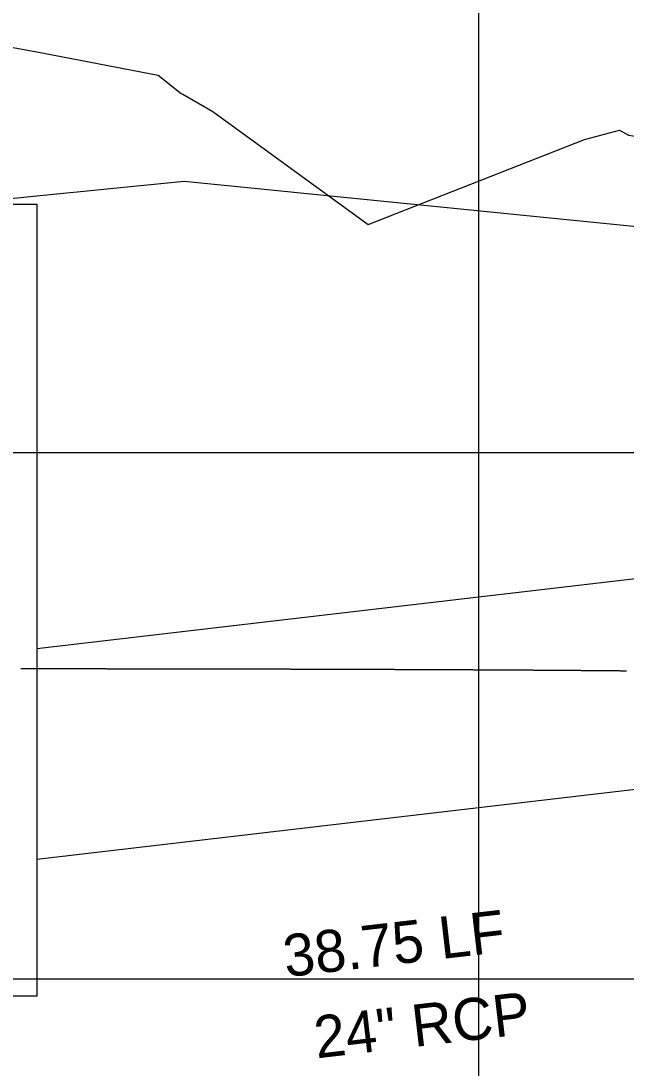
# Model space of a CAD drawing. Extents: x 2252703 to 2264864, y 13787568 to 13790989.
# Drawn here: x 2264616.92 to 2264645.67, y 13788381.55 to 13788431.28 of the extents above; entities that cross this region are included whole.
import ezdxf

# ---------------------------------------------------------------- set-up
doc = ezdxf.new("R2010")
doc.units = 0
for name, color, linetype in [('BORD_grid_bottom_major_5int', 7, 'Continuous'), ('D_DRN_PROF_HGL', 7, 'Continuous'), ('D_PROF_1', 7, 'Continuous'), ('D_PROF_NOTES_1', 7, 'Continuous'), ('Drain_PipeInside', 7, 'Continuous'), ('E_Terrain', 7, 'Continuous'), ('Inlet', 7, 'Continuous'), ('z - Construction', 7, 'Continuous')]:
    doc.layers.add(name, color=color, linetype=linetype)

msp = doc.modelspace()

# ---------------------------------------------------------------- linework, layer by layer
at = {"layer": 'BORD_grid_bottom_major_5int'}
for p, q in [((2264638.672, 13788310.788), (2264638.672, 13788610.788)), ((2264413.672, 13788410.788), (2264763.672, 13788410.788)), ((2264413.672, 13788385.788), (2264763.672, 13788385.788))]:
    msp.add_line(p, q, dxfattribs=at)
at = {"layer": 'D_DRN_PROF_HGL'}
msp.add_lwpolyline([(2264616.909, 13788400.52), (2264616.952, 13788400.52), (2264616.994, 13788400.52), (2264617.037, 13788400.52), (2264617.079, 13788400.52), (2264617.122, 13788400.52), (2264617.164, 13788400.52), (2264617.207, 13788400.52), (2264617.249, 13788400.519), (2264617.292, 13788400.519), (2264617.334, 13788400.519), (2264617.377, 13788400.519), (2264617.419, 13788400.519), (2264617.462, 13788400.519), (2264617.505, 13788400.519), (2264617.547, 13788400.519), (2264617.59, 13788400.519), (2264617.632, 13788400.519), (2264617.675, 13788400.519), (2264617.717, 13788400.519), (2264617.76, 13788400.519), (2264617.802, 13788400.519), (2264617.845, 13788400.519), (2264617.887, 13788400.519), (2264617.93, 13788400.519), (2264617.972, 13788400.519), (2264618.015, 13788400.519), (2264618.057, 13788400.519), (2264618.1, 13788400.519), (2264618.142, 13788400.519), (2264618.185, 13788400.519), (2264618.227, 13788400.519), (2264618.27, 13788400.519), (2264618.312, 13788400.518), (2264618.355, 13788400.518), (2264618.397, 13788400.518), (2264618.44, 13788400.518), (2264618.482, 13788400.518), (2264618.525, 13788400.518), (2264618.567, 13788400.518), (2264618.61, 13788400.518), (2264618.652, 13788400.518), (2264618.695, 13788400.518), (2264618.737, 13788400.518), (2264618.78, 13788400.518), (2264618.822, 13788400.518), (2264618.865, 13788400.518), (2264618.907, 13788400.518), (2264618.95, 13788400.518), (2264618.992, 13788400.518), (2264619.035, 13788400.518), (2264619.077, 13788400.518), (2264619.12, 13788400.518), (2264619.162, 13788400.518), (2264619.204, 13788400.518), (2264619.247, 13788400.518), (2264619.289, 13788400.517), (2264619.332, 13788400.517), (2264619.374, 13788400.517), (2264619.417, 13788400.517), (2264619.459, 13788400.517), (2264619.502, 13788400.517), (2264619.544, 13788400.517), (2264619.587, 13788400.517), (2264619.629, 13788400.517), (2264619.672, 13788400.517), (2264619.714, 13788400.517), (2264619.756, 13788400.517), (2264619.799, 13788400.517), (2264619.841, 13788400.517), (2264619.884, 13788400.517), (2264619.926, 13788400.517), (2264619.969, 13788400.517), (2264620.011, 13788400.517), (2264620.054, 13788400.517), (2264620.096, 13788400.517), (2264620.138, 13788400.516), (2264620.181, 13788400.516), (2264620.223, 13788400.516), (2264620.266, 13788400.516), (2264620.308, 13788400.516), (2264620.351, 13788400.516), (2264620.393, 13788400.516), (2264620.435, 13788400.516), (2264620.478, 13788400.516), (2264620.52, 13788400.516), (2264620.563, 13788400.516), (2264620.605, 13788400.516), (2264620.648, 13788400.516), (2264620.69, 13788400.516), (2264620.732, 13788400.516), (2264620.775, 13788400.516), (2264620.817, 13788400.516), (2264620.86, 13788400.516), (2264620.902, 13788400.516), (2264620.944, 13788400.516), (2264620.987, 13788400.515), (2264621.029, 13788400.515), (2264621.072, 13788400.515), (2264621.114, 13788400.515), (2264621.156, 13788400.515), (2264621.199, 13788400.515), (2264621.241, 13788400.515), (2264621.284, 13788400.515), (2264621.326, 13788400.515), (2264621.368, 13788400.515), (2264621.411, 13788400.515), (2264621.453, 13788400.515), (2264621.496, 13788400.515), (2264621.538, 13788400.515), (2264621.58, 13788400.515), (2264621.623, 13788400.515), (2264621.665, 13788400.515), (2264621.707, 13788400.515), (2264621.75, 13788400.514), (2264621.792, 13788400.514), (2264621.835, 13788400.514), (2264621.877, 13788400.514), (2264621.919, 13788400.514), (2264621.962, 13788400.514), (2264622.004, 13788400.514), (2264622.046, 13788400.514), (2264622.089, 13788400.514), (2264622.131, 13788400.514), (2264622.173, 13788400.514), (2264622.216, 13788400.514), (2264622.258, 13788400.514), (2264622.3, 13788400.514), (2264622.343, 13788400.514), (2264622.385, 13788400.514), (2264622.428, 13788400.514), (2264622.47, 13788400.513), (2264622.512, 13788400.513), (2264622.555, 13788400.513), (2264622.597, 13788400.513), (2264622.639, 13788400.513), (2264622.682, 13788400.513), (2264622.724, 13788400.513), (2264622.766, 13788400.513), (2264622.809, 13788400.513), (2264622.851, 13788400.513), (2264622.893, 13788400.513), (2264622.936, 13788400.513), (2264622.978, 13788400.513), (2264623.02, 13788400.513), (2264623.063, 13788400.513), (2264623.105, 13788400.513), (2264623.147, 13788400.512), (2264623.189, 13788400.512), (2264623.232, 13788400.512), (2264623.274, 13788400.512), (2264623.316, 13788400.512), (2264623.359, 13788400.512), (2264623.401, 13788400.512), (2264623.443, 13788400.512), (2264623.486, 13788400.512), (2264623.528, 13788400.512), (2264623.57, 13788400.512), (2264623.613, 13788400.512), (2264623.655, 13788400.512), (2264623.697, 13788400.512), (2264623.739, 13788400.512), (2264623.782, 13788400.511), (2264623.824, 13788400.511), (2264623.866, 13788400.511), (2264623.909, 13788400.511), (2264623.951, 13788400.511), (2264623.993, 13788400.511), (2264624.035, 13788400.511), (2264624.078, 13788400.511), (2264624.12, 13788400.511), (2264624.162, 13788400.511), (2264624.205, 13788400.511), (2264624.247, 13788400.511), (2264624.289, 13788400.511), (2264624.331, 13788400.511), (2264624.374, 13788400.511), (2264624.416, 13788400.51), (2264624.458, 13788400.51), (2264624.5, 13788400.51), (2264624.543, 13788400.51), (2264624.585, 13788400.51), (2264624.627, 13788400.51), (2264624.669, 13788400.51), (2264624.712, 13788400.51), (2264624.754, 13788400.51), (2264624.796, 13788400.51), (2264624.838, 13788400.51), (2264624.881, 13788400.51), (2264624.923, 13788400.51), (2264624.965, 13788400.509), (2264625.007, 13788400.509), (2264625.049, 13788400.509), (2264625.092, 13788400.509), (2264625.134, 13788400.509), (2264625.176, 13788400.509), (2264625.218, 13788400.509), (2264625.261, 13788400.509), (2264625.303, 13788400.509), (2264625.345, 13788400.509), (2264625.387, 13788400.509), (2264625.429, 13788400.509), (2264625.472, 13788400.509), (2264625.514, 13788400.509), (2264625.556, 13788400.508), (2264625.598, 13788400.508), (2264625.641, 13788400.508), (2264625.683, 13788400.508), (2264625.725, 13788400.508), (2264625.767, 13788400.508), (2264625.809, 13788400.508), (2264625.851, 13788400.508), (2264625.894, 13788400.508), (2264625.936, 13788400.508), (2264625.978, 13788400.508), (2264626.02, 13788400.508), (2264626.062, 13788400.507), (2264626.105, 13788400.507), (2264626.147, 13788400.507), (2264626.189, 13788400.507), (2264626.231, 13788400.507), (2264626.273, 13788400.507), (2264626.315, 13788400.507), (2264626.358, 13788400.507), (2264626.4, 13788400.507), (2264626.442, 13788400.507), (2264626.484, 13788400.507), (2264626.526, 13788400.507), (2264626.568, 13788400.507), (2264626.611, 13788400.506), (2264626.653, 13788400.506), (2264626.695, 13788400.506), (2264626.737, 13788400.506), (2264626.779, 13788400.506), (2264626.821, 13788400.506), (2264626.863, 13788400.506), (2264626.906, 13788400.506), (2264626.948, 13788400.506), (2264626.99, 13788400.506), (2264627.032, 13788400.506), (2264627.074, 13788400.506), (2264627.116, 13788400.505), (2264627.158, 13788400.505), (2264627.2, 13788400.505), (2264627.243, 13788400.505), (2264627.285, 13788400.505), (2264627.327, 13788400.505), (2264627.369, 13788400.505), (2264627.411, 13788400.505), (2264627.453, 13788400.505), (2264627.495, 13788400.505), (2264627.537, 13788400.505), (2264627.579, 13788400.504), (2264627.622, 13788400.504), (2264627.664, 13788400.504), (2264627.706, 13788400.504), (2264627.748, 13788400.504), (2264627.79, 13788400.504), (2264627.832, 13788400.504), (2264627.874, 13788400.504), (2264627.916, 13788400.504), (2264627.958, 13788400.504), (2264628, 13788400.504), (2264628.042, 13788400.503), (2264628.084, 13788400.503), (2264628.126, 13788400.503), (2264628.169, 13788400.503), (2264628.211, 13788400.503), (2264628.253, 13788400.503), (2264628.295, 13788400.503), (2264628.337, 13788400.503), (2264628.379, 13788400.503), (2264628.421, 13788400.503), (2264628.463, 13788400.503), (2264628.505, 13788400.502), (2264628.547, 13788400.502), (2264628.589, 13788400.502), (2264628.631, 13788400.502), (2264628.673, 13788400.502), (2264628.715, 13788400.502), (2264628.757, 13788400.502), (2264628.799, 13788400.502), (2264628.841, 13788400.502), (2264628.883, 13788400.502), (2264628.925, 13788400.501), (2264628.967, 13788400.501), (2264629.009, 13788400.501), (2264629.051, 13788400.501), (2264629.093, 13788400.501), (2264629.135, 13788400.501), (2264629.177, 13788400.501), (2264629.219, 13788400.501), (2264629.261, 13788400.501), (2264629.303, 13788400.501), (2264629.345, 13788400.5), (2264629.387, 13788400.5), (2264629.429, 13788400.5), (2264629.471, 13788400.5), (2264629.513, 13788400.5), (2264629.555, 13788400.5), (2264629.597, 13788400.5), (2264629.639, 13788400.5), (2264629.681, 13788400.5), (2264629.723, 13788400.5), (2264629.765, 13788400.499), (2264629.807, 13788400.499), (2264629.849, 13788400.499), (2264629.891, 13788400.499), (2264629.933, 13788400.499), (2264629.975, 13788400.499), (2264630.017, 13788400.499), (2264630.059, 13788400.499), (2264630.101, 13788400.499), (2264630.143, 13788400.498), (2264630.185, 13788400.498), (2264630.227, 13788400.498), (2264630.268, 13788400.498), (2264630.31, 13788400.498), (2264630.352, 13788400.498), (2264630.394, 13788400.498), (2264630.436, 13788400.498), (2264630.478, 13788400.498), (2264630.52, 13788400.497), (2264630.562, 13788400.497), (2264630.604, 13788400.497), (2264630.646, 13788400.497), (2264630.688, 13788400.497), (2264630.729, 13788400.497), (2264630.771, 13788400.497), (2264630.813, 13788400.497), (2264630.855, 13788400.497), (2264630.897, 13788400.496), (2264630.939, 13788400.496), (2264630.981, 13788400.496), (2264631.023, 13788400.496), (2264631.065, 13788400.496), (2264631.106, 13788400.496), (2264631.148, 13788400.496), (2264631.19, 13788400.496), (2264631.232, 13788400.496), (2264631.274, 13788400.495), (2264631.316, 13788400.495), (2264631.358, 13788400.495), (2264631.399, 13788400.495), (2264631.441, 13788400.495), (2264631.483, 13788400.495), (2264631.525, 13788400.495), (2264631.567, 13788400.495), (2264631.609, 13788400.494), (2264631.65, 13788400.494), (2264631.692, 13788400.494), (2264631.734, 13788400.494), (2264631.776, 13788400.494), (2264631.818, 13788400.494), (2264631.86, 13788400.494), (2264631.901, 13788400.494), (2264631.943, 13788400.493), (2264631.985, 13788400.493), (2264632.027, 13788400.493), (2264632.069, 13788400.493), (2264632.11, 13788400.493), (2264632.152, 13788400.493), (2264632.194, 13788400.493), (2264632.236, 13788400.493), (2264632.277, 13788400.492), (2264632.319, 13788400.492), (2264632.361, 13788400.492), (2264632.403, 13788400.492), (2264632.445, 13788400.492), (2264632.486, 13788400.492), (2264632.528, 13788400.492), (2264632.57, 13788400.492), (2264632.612, 13788400.491), (2264632.653, 13788400.491), (2264632.695, 13788400.491), (2264632.737, 13788400.491), (2264632.779, 13788400.491), (2264632.82, 13788400.491), (2264632.862, 13788400.491), (2264632.904, 13788400.491), (2264632.945, 13788400.49), (2264632.987, 13788400.49), (2264633.029, 13788400.49), (2264633.071, 13788400.49), (2264633.112, 13788400.49), (2264633.154, 13788400.49), (2264633.196, 13788400.49), (2264633.237, 13788400.489), (2264633.279, 13788400.489), (2264633.321, 13788400.489), (2264633.362, 13788400.489), (2264633.404, 13788400.489), (2264633.446, 13788400.489), (2264633.488, 13788400.489), (2264633.529, 13788400.488), (2264633.571, 13788400.488), (2264633.613, 13788400.488), (2264633.654, 13788400.488), (2264633.696, 13788400.488), (2264633.737, 13788400.488), (2264633.779, 13788400.488), (2264633.821, 13788400.487), (2264633.862, 13788400.487), (2264633.904, 13788400.487), (2264633.946, 13788400.487), (2264633.987, 13788400.487), (2264634.029, 13788400.487), (2264634.071, 13788400.487), (2264634.112, 13788400.486), (2264634.154, 13788400.486), (2264634.195, 13788400.486), (2264634.237, 13788400.486), (2264634.279, 13788400.486), (2264634.32, 13788400.486), (2264634.362, 13788400.486), (2264634.403, 13788400.485), (2264634.445, 13788400.485), (2264634.487, 13788400.485), (2264634.528, 13788400.485), (2264634.57, 13788400.485), (2264634.611, 13788400.485), (2264634.653, 13788400.485), (2264634.694, 13788400.484), (2264634.736, 13788400.484), (2264634.777, 13788400.484), (2264634.819, 13788400.484), (2264634.861, 13788400.484), (2264634.902, 13788400.484), (2264634.944, 13788400.483), (2264634.985, 13788400.483), (2264635.027, 13788400.483), (2264635.068, 13788400.483), (2264635.11, 13788400.483), (2264635.151, 13788400.483), (2264635.193, 13788400.483), (2264635.234, 13788400.482), (2264635.276, 13788400.482), (2264635.317, 13788400.482), (2264635.359, 13788400.482), (2264635.4, 13788400.482), (2264635.442, 13788400.482), (2264635.483, 13788400.481), (2264635.525, 13788400.481), (2264635.566, 13788400.481), (2264635.608, 13788400.481), (2264635.649, 13788400.481), (2264635.691, 13788400.481), (2264635.732, 13788400.48), (2264635.773, 13788400.48), (2264635.815, 13788400.48), (2264635.856, 13788400.48), (2264635.898, 13788400.48), (2264635.939, 13788400.48), (2264635.981, 13788400.479), (2264636.022, 13788400.479), (2264636.063, 13788400.479), (2264636.105, 13788400.479), (2264636.146, 13788400.479), (2264636.188, 13788400.479), (2264636.229, 13788400.478), (2264636.27, 13788400.478), (2264636.312, 13788400.478), (2264636.353, 13788400.478), (2264636.395, 13788400.478), (2264636.436, 13788400.478), (2264636.477, 13788400.477), (2264636.519, 13788400.477), (2264636.56, 13788400.477), (2264636.601, 13788400.477), (2264636.643, 13788400.477), (2264636.684, 13788400.476), (2264636.725, 13788400.476), (2264636.767, 13788400.476), (2264636.808, 13788400.476), (2264636.849, 13788400.476), (2264636.891, 13788400.476), (2264636.932, 13788400.475), (2264636.973, 13788400.475), (2264637.015, 13788400.475), (2264637.056, 13788400.475), (2264637.097, 13788400.475), (2264637.138, 13788400.474), (2264637.18, 13788400.474), (2264637.221, 13788400.474), (2264637.262, 13788400.474), (2264637.304, 13788400.474), (2264637.345, 13788400.474), (2264637.386, 13788400.473), (2264637.427, 13788400.473), (2264637.469, 13788400.473), (2264637.51, 13788400.473), (2264637.551, 13788400.473), (2264637.592, 13788400.472), (2264637.634, 13788400.472), (2264637.675, 13788400.472), (2264637.716, 13788400.472), (2264637.757, 13788400.472), (2264637.798, 13788400.471), (2264637.84, 13788400.471), (2264637.881, 13788400.471), (2264637.922, 13788400.471), (2264637.963, 13788400.471), (2264638.004, 13788400.47), (2264638.045, 13788400.47), (2264638.087, 13788400.47), (2264638.128, 13788400.47), (2264638.169, 13788400.47), (2264638.21, 13788400.469), (2264638.251, 13788400.469), (2264638.292, 13788400.469), (2264638.333, 13788400.469), (2264638.375, 13788400.469), (2264638.416, 13788400.468), (2264638.457, 13788400.468), (2264638.498, 13788400.468), (2264638.539, 13788400.468), (2264638.58, 13788400.468), (2264638.621, 13788400.467), (2264638.662, 13788400.467), (2264638.703, 13788400.467), (2264638.744, 13788400.467), (2264638.785, 13788400.467), (2264638.827, 13788400.466), (2264638.868, 13788400.466), (2264638.909, 13788400.466), (2264638.95, 13788400.466), (2264638.991, 13788400.466), (2264639.032, 13788400.465), (2264639.073, 13788400.465), (2264639.114, 13788400.465), (2264639.155, 13788400.465), (2264639.196, 13788400.464), (2264639.237, 13788400.464), (2264639.278, 13788400.464), (2264639.319, 13788400.464), (2264639.36, 13788400.464), (2264639.401, 13788400.463), (2264639.442, 13788400.463), (2264639.483, 13788400.463), (2264639.524, 13788400.463), (2264639.564, 13788400.462), (2264639.605, 13788400.462), (2264639.646, 13788400.462), (2264639.687, 13788400.462), (2264639.728, 13788400.462), (2264639.769, 13788400.461), (2264639.81, 13788400.461), (2264639.851, 13788400.461), (2264639.892, 13788400.461), (2264639.933, 13788400.46), (2264639.974, 13788400.46), (2264640.014, 13788400.46), (2264640.055, 13788400.46), (2264640.096, 13788400.459), (2264640.137, 13788400.459), (2264640.178, 13788400.459), (2264640.219, 13788400.459), (2264640.259, 13788400.459), (2264640.3, 13788400.458), (2264640.341, 13788400.458), (2264640.382, 13788400.458), (2264640.423, 13788400.458), (2264640.463, 13788400.457), (2264640.504, 13788400.457), (2264640.545, 13788400.457), (2264640.586, 13788400.457), (2264640.627, 13788400.456), (2264640.667, 13788400.456), (2264640.708, 13788400.456), (2264640.749, 13788400.456), (2264640.79, 13788400.455), (2264640.83, 13788400.455), (2264640.871, 13788400.455), (2264640.912, 13788400.455), (2264640.952, 13788400.454), (2264640.993, 13788400.454), (2264641.034, 13788400.454), (2264641.075, 13788400.454), (2264641.115, 13788400.453), (2264641.156, 13788400.453), (2264641.197, 13788400.453), (2264641.237, 13788400.453), (2264641.278, 13788400.452), (2264641.318, 13788400.452), (2264641.359, 13788400.452), (2264641.4, 13788400.452), (2264641.44, 13788400.451), (2264641.481, 13788400.451), (2264641.522, 13788400.451), (2264641.562, 13788400.45), (2264641.603, 13788400.45), (2264641.643, 13788400.45), (2264641.684, 13788400.45), (2264641.724, 13788400.449), (2264641.765, 13788400.449), (2264641.805, 13788400.449), (2264641.846, 13788400.449), (2264641.887, 13788400.448), (2264641.927, 13788400.448), (2264641.968, 13788400.448), (2264642.008, 13788400.447), (2264642.049, 13788400.447), (2264642.089, 13788400.447), (2264642.129, 13788400.447), (2264642.17, 13788400.446), (2264642.21, 13788400.446), (2264642.251, 13788400.446), (2264642.291, 13788400.446), (2264642.332, 13788400.445), (2264642.372, 13788400.445), (2264642.413, 13788400.445), (2264642.453, 13788400.444), (2264642.493, 13788400.444), (2264642.534, 13788400.444), (2264642.574, 13788400.444), (2264642.614, 13788400.443), (2264642.655, 13788400.443), (2264642.695, 13788400.443), (2264642.736, 13788400.442), (2264642.776, 13788400.442), (2264642.816, 13788400.442), (2264642.857, 13788400.441), (2264642.897, 13788400.441), (2264642.937, 13788400.441), (2264642.977, 13788400.441), (2264643.018, 13788400.44), (2264643.058, 13788400.44), (2264643.098, 13788400.44), (2264643.138, 13788400.439), (2264643.179, 13788400.439), (2264643.219, 13788400.439), (2264643.259, 13788400.438), (2264643.299, 13788400.438), (2264643.34, 13788400.438), (2264643.38, 13788400.437), (2264643.42, 13788400.437), (2264643.46, 13788400.437), (2264643.5, 13788400.437), (2264643.54, 13788400.436), (2264643.581, 13788400.436), (2264643.621, 13788400.436), (2264643.661, 13788400.435), (2264643.701, 13788400.435), (2264643.741, 13788400.435), (2264643.781, 13788400.434), (2264643.821, 13788400.434), (2264643.861, 13788400.434), (2264643.901, 13788400.433), (2264643.941, 13788400.433), (2264643.981, 13788400.433), (2264644.021, 13788400.432), (2264644.061, 13788400.432), (2264644.101, 13788400.432), (2264644.141, 13788400.431), (2264644.181, 13788400.431), (2264644.221, 13788400.431), (2264644.261, 13788400.43), (2264644.301, 13788400.43), (2264644.341, 13788400.43), (2264644.381, 13788400.429), (2264644.421, 13788400.429), (2264644.461, 13788400.429), (2264644.501, 13788400.428), (2264644.541, 13788400.428), (2264644.581, 13788400.428), (2264644.621, 13788400.427), (2264644.66, 13788400.427), (2264644.7, 13788400.427), (2264644.74, 13788400.426), (2264644.78, 13788400.426), (2264644.82, 13788400.425), (2264644.86, 13788400.425), (2264644.899, 13788400.425), (2264644.939, 13788400.424), (2264644.979, 13788400.424), (2264645.019, 13788400.424), (2264645.058, 13788400.423), (2264645.098, 13788400.423), (2264645.138, 13788400.423), (2264645.178, 13788400.422), (2264645.217, 13788400.422), (2264645.257, 13788400.421), (2264645.297, 13788400.421), (2264645.336, 13788400.421), (2264645.376, 13788400.42), (2264645.416, 13788400.42), (2264645.455, 13788400.42), (2264645.495, 13788400.419), (2264645.534, 13788400.419), (2264645.574, 13788400.418), (2264645.614, 13788400.418), (2264645.653, 13788400.418), (2264645.693, 13788400.417)], dxfattribs=at)
at = {"layer": 'D_PROF_1'}
msp.add_lwpolyline([(2264613.672, 13788422.562), (2264617.672, 13788422.967), (2264617.672, 13788422.967), (2264624.672, 13788423.675), (2264655.672, 13788420.575), (2264655.901, 13788421.594), (2264656.422, 13788423.908), (2264656.422, 13788423.908), (2264657.922, 13788424.058)], dxfattribs=at)
at = {"layer": 'Drain_PipeInside'}
for p, q in [((2264617.672, 13788401.473), (2264656.422, 13788405.993)), ((2264617.672, 13788391.473), (2264656.422, 13788395.993))]:
    msp.add_line(p, q, dxfattribs=at)
at = {"layer": 'E_Terrain'}
msp.add_lwpolyline([(2264613.672, 13788430.519), (2264616.733, 13788429.991), (2264617.672, 13788429.811), (2264617.672, 13788429.811), (2264623.449, 13788428.698), (2264624.527, 13788427.828), (2264624.606, 13788427.799), (2264626.031, 13788426.981), (2264633.42, 13788421.619), (2264643.69, 13788425.651), (2264645.365, 13788426.099), (2264645.783, 13788425.86), (2264649.676, 13788425.264), (2264656.422, 13788424.521), (2264656.422, 13788424.521), (2264657.922, 13788424.356)], dxfattribs=at)
at = {"layer": 'Inlet'}
msp.add_lwpolyline([(2264613.672, 13788422.575), (2264617.672, 13788422.575), (2264617.672, 13788384.959), (2264613.672, 13788384.959)], close=True, dxfattribs=at)
at = {"layer": 'z - Construction'}
for p, q in [((2264613.672, 13788410.788), (2264657.922, 13788410.788)), ((2264613.672, 13788385.788), (2264657.922, 13788385.788))]:
    msp.add_line(p, q, dxfattribs=at)

# ---------------------------------------------------------------- texts
at = {"layer": 'D_PROF_NOTES_1'}
for s, p in [('38.75 LF', (2264629.509, 13788385.86)), ('24" RCP', (2264630.973, 13788382.004))]:
    msp.add_text(s, height=2, rotation=6.6532, dxfattribs=at).set_placement(p)

doc.saveas('drawing.dxf')
